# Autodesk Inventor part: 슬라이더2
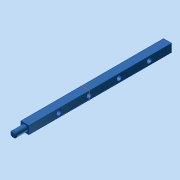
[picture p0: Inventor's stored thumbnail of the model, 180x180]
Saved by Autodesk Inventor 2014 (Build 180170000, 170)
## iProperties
Company: 한국ATC센터
Created: 2015-04
Part Number: 슬라이더2
Document SubType Name: Modeling
Designer: KYOUNG IL JANG
Density: 7.85 g/cm^3
Material: 강
Appearance: 하늘색 짙음
Author: KYOUNG IL JANG
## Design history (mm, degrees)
sketch "스케치3"
  geometry: L1 (4, 142)-(-4, 142); L2 (-4, 142)-(-4, 0); L3 (-4, 0)-(4, 0); L4 (4, 0)-(4, 142); 3 further points
  constraints: 8 end point, 2 coincident, 2 parallel, 1 horizontal, 1 midpoint, 1 perpendicular
  dimensions: "d5" = 8 distance of L1.start L1.end; "d6" = 142 distance of L1.end L2.end
extrude "돌출3" new body sketch "스케치3" stored distance "d7" = 8; taper "d8" = 0 deg
sketch "스케치4"
  geometry: L1 (8, 0)-(0, 0) reference; 3 further points
  constraints: 1 midpoint, 1 vertical alignment
  dimensions: "d9" = 30 distance of point (4, 30) point (4, 0)
hole "구멍1" sketch "스케치4" at (4, 30) diameter "d10" = 5; stored, may be unused: countersink angle "d14" = 90 deg, drill point angle "d16" = 118 deg; dims "d11" = 6, "d12" = 4, "d13" = 2, "d15" = 8
sketch "스케치5"
  geometry: C1 r 3 at (4, -4); 1 further point
  constraints: 1 centre point, 1 coincident
  dimensions: "d20" = 6 diameter of C1
extrude "돌출4" join sketch "스케치5" distance "d21" = 12; taper "d22" = 0 deg
chamfer "모따기1" distance "d23" = 1; stored, may be unused: second distance "d24" = 2, angle "d25" = 45 deg
node "작업 평면2"
  node "작업축1"
node "솔리드1"
pattern_linear "직사각형 패턴1" dims "d19" = 30
node "솔리드2"
other parameters: "d26" = 0
